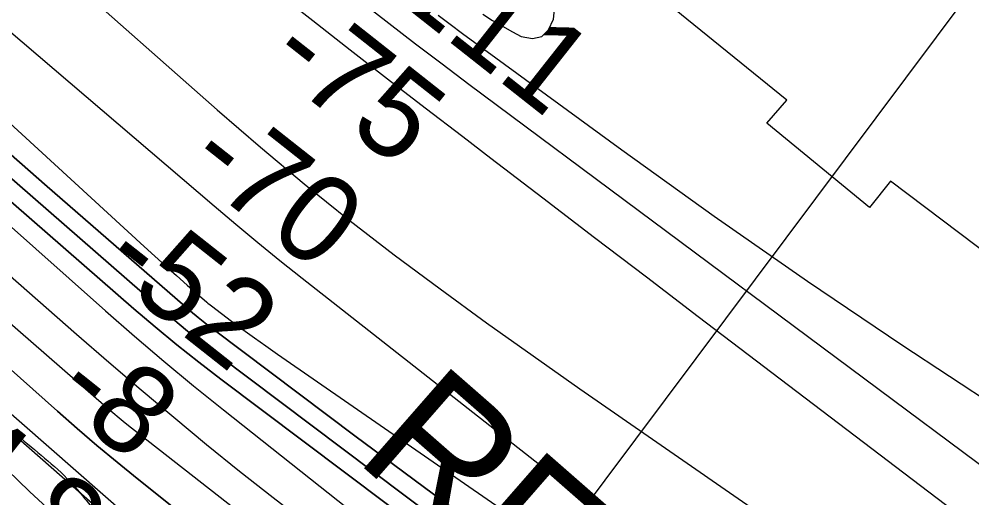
# Model space of a CAD drawing. Extents: x 3823584 to 3861785, y 301729 to 327625.
# Drawn here: x 3838296 to 3839018, y 323662 to 324025 of the extents above; entities that cross this region are included whole.
import ezdxf

# ---------------------------------------------------------------- set-up
doc = ezdxf.new("R2010")
doc.units = 0
for name, color, linetype in [('V-GRID-MAJR', 7, 'Continuous'), ('V-RIVR-EDGE', 7, 'Continuous'), ('V-RIVR-RANG', 7, 'Continuous'), ('V-RRAP-FSHR', 7, 'Continuous'), ('V-RRAP-RVMT', 7, 'Continuous'), ('V-RRAP-RVMT-IDEN', 7, 'Continuous'), ('V-SITE-VEGE', 7, 'Continuous'), ('V-TOPO-DPTH', 7, 'Continuous'), ('V-TOPO-MAJR', 7, 'Continuous'), ('V-TOPO-MINR', 7, 'Continuous'), ('V-TOPO-WATR', 7, 'Continuous')]:
    doc.layers.add(name, color=color, linetype=linetype)

msp = doc.modelspace()

# ---------------------------------------------------------------- linework, layer by layer
at = {"layer": 'V-GRID-MAJR'}
msp.add_spline([(3838444.89, 307319.34), (3838352.38, 313376.37), (3838259.82, 319436.47), (3838167.27, 325496.58), (3838167.22, 325499.66)], degree=3, dxfattribs=at)
at = {"layer": 'V-RIVR-EDGE'}
msp.add_spline([(3836304.38, 325474.18), (3836346.41, 325438.32), (3836389.41, 325406.07), (3836417.64, 325385.43), (3836442.67, 325366.73), (3836470.25, 325340.95), (3836497.82, 325313.88), (3836554.9, 325258.45), (3836598.51, 325215.91), (3836636.36, 325181.1), (3836681.26, 325139.85), (3836737.07, 325093.42), (3836790.94, 325041.22), (3836840.33, 324993.52), (3836889.07, 324947.12), (3836934.61, 324907.14), (3836980.81, 324871.03), (3837015.47, 324849.09), (3837040.49, 324829.1), (3837085.39, 324787.2), (3837143.76, 324734.34), (3837181.61, 324700.82), (3837223.29, 324659.57), (3837272.05, 324619.59), (3837314.38, 324579.63), (3837346.45, 324546.76), (3837364.4, 324527.43), (3837395.83, 324500.35), (3837442.02, 324462.31), (3837492.71, 324422.97), (3837554.31, 324372.67), (3837573.56, 324361.05), (3837583.2, 324359.1), (3837596.69, 324352.64), (3837621.08, 324337.79), (3837648.03, 324319.73), (3837677.54, 324292.01), (3837718.58, 324249.48), (3837753.85, 324214.68), (3837781.43, 324188.89), (3837800.05, 324179.85), (3837819.95, 324170.8), (3837850.72, 324134.08), (3837874.45, 324110.23), (3837909.07, 324073.5), (3837941.78, 324040.64), (3837989.87, 323991.66), (3838022.58, 323960.72), (3838034.12, 323947.83), (3838046.3, 323933.66), (3838066.83, 323916.25), (3838089.91, 323892.41), (3838140.59, 323849.21), (3838186.14, 323811.17), (3838215.65, 323785.38), (3838265.68, 323736.4), (3838297.1, 323707.39), (3838336.87, 323671.94), (3838359.95, 323645.52), (3838385.62, 323627.46), (3838404.24, 323615.84), (3838421.56, 323601.65), (3838441.44, 323582.32), (3838460.05, 323567.49), (3838468.4, 323563.61), (3838484.45, 323555.21), (3838548.59, 323496.55), (3838595.44, 323464.29), (3838649.98, 323422.37), (3838701.3, 323379.82), (3838749.43, 323345.62), (3838798.22, 323317.86), (3838856.62, 323274.64), (3838932.99, 323221.74), (3838989.47, 323184.31), (3839037.6, 323150.12), (3839068.42, 323134.62), (3839093.42, 323104.98), (3839110.73, 323086.94), (3839122.93, 323081.12), (3839143.46, 323065.64), (3839172.34, 323044.36), (3839190.96, 323032.74), (3839215.99, 323015.96), (3839242.32, 323006.26), (3839316.8, 322969.43), (3839341.84, 322955.87), (3839371.38, 322944.22), (3839391.29, 322935.81), (3839417.61, 322920.32), (3839461.26, 322894.5), (3839483.71, 322873.23), (3839520.3, 322851.28), (3839555.6, 322828.69), (3839599.9, 322806.72), (3839718.7, 322751.14), (3839768.14, 322726.59), (3839807.95, 322705.92), (3839836.85, 322696.21), (3839865.1, 322680.71), (3839887.57, 322667.8), (3839924.17, 322652.28), (3839969.76, 322630.31), (3840004.43, 322612.22), (3840037.82, 322597.35), (3840085.35, 322579.88), (3840108.46, 322565.68), (3840121.92, 322548.93), (3840123.18, 322539.92), (3840122.53, 322533.5), (3840118, 322521.29), (3840112.84, 322514.24), (3840095.47, 322509.14), (3840089.68, 322509.15), (3840085.17, 322504.66), (3840084.51, 322498.23), (3840085.78, 322491.8), (3840130.72, 322467.26), (3840169.89, 322448.52), (3840197.51, 322439.45), (3840209.08, 322437.5), (3840231.59, 322441.3), (3840246.39, 322448.98), (3840266.34, 322458.57), (3840273.43, 322466.27), (3840278.59, 322471.4), (3840288.9, 322480.37), (3840295.98, 322484.85), (3840301.77, 322484.84), (3840308.2, 322484.82), (3840320.4, 322479.01), (3840324.87, 322470), (3840326.78, 322461.63), (3840338.32, 322450.03), (3840344.74, 322444.88), (3840366.58, 322437.75), (3840385.84, 322428.06), (3840421.8, 322409.33), (3840466.1, 322385.43), (3840492.41, 322368.65), (3840506.53, 322357.04), (3840533.49, 322340.26), (3840559.18, 322331.2), (3840587.44, 322322.13), (3840611.85, 322311.78), (3840642.02, 322296.28), (3840678.62, 322276.26), (3840712.64, 322255.6), (3840733.18, 322242.05), (3840784.53, 322210.43), (3840835.89, 322183.3), (3840892.39, 322153.59), (3840923.85, 322139.37), (3840950.82, 322127.08), (3840989.33, 322099.99), (3841017.57, 322082.56), (3841061.24, 322062.52), (3841092.69, 322044.45), (3841151.1, 322005.09), (3841210.78, 321964.44), (3841240.29, 321939.29), (3841299.97, 321894.79), (3841335.89, 321862.55), (3841374.37, 321823.89), (3841411.57, 321789.72), (3841444.92, 321758.14), (3841469.94, 321736.22), (3841482.12, 321723.98), (3841496.22, 321704.66), (3841509.05, 321694.34), (3841523.18, 321687.23), (3841573.9, 321660.75), (3841623.97, 321631.69), (3841667.62, 321606.51), (3841696.52, 321593.59), (3841738.26, 321575.48), (3841787.07, 321556.72), (3841815.99, 321552.15), (3841851.33, 321544.99), (3841886.66, 321533.33), (3841930.32, 321511.36), (3841950.22, 321498.46), (3841977.18, 321482.96), (3841998.38, 321476.48), (3842052.99, 321463.49), (3842082.55, 321456.34), (3842109.52, 321444.7), (3842146.12, 321427.26), (3842196.2, 321402.06), (3842241.13, 321374.95), (3842288.63, 321345.26), (3842321.38, 321327.18), (3842366.94, 321295.56), (3842395.19, 321280.07), (3842429.22, 321264.55), (3842452.35, 321258.71), (3842470.97, 321249.66)], degree=3, dxfattribs=at)
at = {"layer": 'V-RIVR-RANG'}
msp.add_line((3838513.47, 323372.9), (3839031.51, 324065.62), dxfattribs=at)
at = {"layer": 'V-RRAP-FSHR'}
msp.add_lwpolyline([(3836295.02, 325470.8), (3836414.5, 325364.56), (3836758, 325057.8), (3837184.26, 324676.32), (3837417.66, 324483.21), (3837615.8, 324305.96), (3837777.41, 324176.43), (3837917.93, 324038.71), (3838584.55, 323453.18)], dxfattribs=at)
at = {"layer": 'V-RRAP-RVMT'}
for p, q in [((3838877.74, 323963.57), (3838787.12, 324036.91)), ((3838862.5, 323946.12), (3838877.74, 323963.57)), ((3838940.35, 323882.38), (3838862.5, 323946.12)), ((3838956.17, 323902.25), (3838940.35, 323882.38)), ((3839067.87, 323817.85), (3838956.17, 323902.25)), ((3838276.69, 323737.31), (3838377.61, 323648.95))]:
    msp.add_line(p, q, dxfattribs=at)
at = {"layer": 'V-SITE-VEGE'}
msp.add_lwpolyline([(3838244.56, 323724.06), (3838303.63, 323667), (3838353.84, 323620.5)], dxfattribs=at)
at = {"layer": 'V-TOPO-DPTH'}
for points in [[(3839047.78, 323301.81), (3838448.68, 323752.1), (3838431.86, 323765.04), (3838415.23, 323778.21), (3838398.88, 323791.75), (3838382.74, 323805.52), (3837860.93, 324260.56)], [(3839047.78, 323301.81), (3838448.68, 323752.1), (3838431.86, 323765.04), (3838415.23, 323778.21), (3838398.88, 323791.75), (3838382.74, 323805.52), (3837860.93, 324260.56)], [(3838153.68, 324022.86), (3838401.16, 323807.21), (3838412.21, 323797.79), (3838423.4, 323788.53), (3838434.78, 323779.51), (3838446.3, 323770.66), (3838752.96, 323540.12), (3838808.46, 323499.01), (3838864.34, 323458.43), (3838920.78, 323418.64), (3838977.6, 323379.38), (3839031.93, 323342.4)], [(3839031.93, 323342.4), (3838977.6, 323379.38), (3838920.78, 323418.64), (3838864.34, 323458.43), (3838808.46, 323499.01), (3838752.96, 323540.12), (3838446.3, 323770.66), (3838434.78, 323779.51), (3838423.4, 323788.53), (3838412.21, 323797.79), (3838401.16, 323807.21), (3838153.68, 324022.86)], [(3839103.1, 323135.17), (3839017.28, 323186.86), (3839013.04, 323189.49), (3839008.84, 323192.19), (3839004.71, 323194.99), (3839000.62, 323197.86), (3838924.64, 323252.69), (3838882.82, 323283.33), (3838841.31, 323314.37), (3838800.26, 323346.02), (3838759.52, 323378.07), (3838385.33, 323676.9), (3838369.99, 323689.35), (3838354.79, 323701.97), (3838339.79, 323714.83), (3838324.93, 323727.85), (3838008.71, 324009.46)], [(3838260.18, 323948.03), (3838317.14, 323898.11), (3838419.59, 323808.9), (3838425.54, 323803.83), (3838431.57, 323798.84), (3838437.7, 323793.98), (3838443.91, 323789.21), (3838550.19, 323709.3), (3838609.87, 323665.03), (3838669.92, 323621.28), (3838730.54, 323578.31), (3838791.52, 323535.86), (3839065.19, 323348)], [(3839065.19, 323348), (3838791.52, 323535.86), (3838730.54, 323578.31), (3838669.92, 323621.28), (3838609.87, 323665.03), (3838550.19, 323709.3), (3838443.91, 323789.21), (3838437.7, 323793.98), (3838431.57, 323798.84), (3838425.54, 323803.83), (3838419.59, 323808.9), (3838317.14, 323898.11), (3838260.18, 323948.03)], [(3838280.38, 323837.73), (3838339.24, 323786.21), (3838363.64, 323765.07), (3838388.18, 323744.08), (3838412.91, 323723.33), (3838437.79, 323702.74), (3838462.92, 323682.48), (3838488.28, 323662.5), (3838513.96, 323642.95), (3838539.86, 323623.68), (3839021.06, 323271.76)], [(3838280.38, 323837.73), (3838339.24, 323786.21), (3838363.64, 323765.07), (3838388.18, 323744.08), (3838412.91, 323723.33), (3838437.79, 323702.74), (3838462.92, 323682.48), (3838488.28, 323662.5), (3838513.96, 323642.95), (3838539.86, 323623.68), (3839021.06, 323271.76)]]:
    msp.add_lwpolyline(points, dxfattribs=at)
at = {"layer": 'V-TOPO-MAJR'}
for points in [[(3837784.65, 324408.95), (3838390.47, 323852.75), (3838398.58, 323845.37), (3838406.73, 323838.03), (3838414.93, 323830.75), (3838423.17, 323823.52), (3838438.02, 323810.6), (3838438.88, 323809.87), (3838440.63, 323808.46), (3838441.52, 323807.77), (3838456.82, 323796.26), (3838465.41, 323789.89), (3838474.05, 323783.58), (3838482.76, 323777.37), (3838491.53, 323771.23), (3839096.12, 323353.07)], [(3838613.26, 324028.04), (3838622.5, 324021.07), (3838631.81, 324014.19), (3838752.51, 323926.07), (3838822.64, 323875.8), (3838893.33, 323826.35), (3838964.85, 323778.12), (3839036.95, 323730.72), (3839242.36, 323598.18), (3839267.15, 323581.94), (3839291.81, 323565.49), (3839316.25, 323548.72), (3839340.54, 323531.74), (3839531.52, 323396.3), (3839611.58, 323339.84), (3839691.82, 323283.66), (3839772.35, 323227.88), (3839853.08, 323172.38), (3839964.66, 323096.08), (3839989.91, 323079.21), (3840015.39, 323062.71), (3840041.23, 323046.77), (3840067.29, 323031.19)]]:
    msp.add_lwpolyline(points, dxfattribs=at)
at = {"layer": 'V-TOPO-MINR'}
for points in [[(3837798.92, 324434.09), (3838443.61, 323883.46), (3838460.11, 323869.55), (3838476.71, 323855.77), (3838493.49, 323842.2), (3838510.38, 323828.77), (3838900.64, 323522.25), (3838938.31, 323493.12), (3838976.26, 323464.38), (3839014.63, 323436.21), (3839053.3, 323408.43)], [(3837715.94, 324378.16), (3838361.3, 323803.95), (3838383.25, 323784.75), (3838405.41, 323765.81), (3838427.9, 323747.25), (3838450.6, 323728.94), (3838603.2, 323608.01), (3838678.68, 323549.08), (3838754.72, 323490.9), (3838831.6, 323433.83), (3838909.05, 323377.5), (3839050.79, 323275.99)], [(3837860.93, 324260.56), (3838382.74, 323805.52), (3838398.88, 323791.75), (3838415.23, 323778.21), (3838431.86, 323765.04), (3838448.68, 323752.1), (3839047.78, 323301.81)], [(3838647.32, 324028.86), (3838654.59, 324024.06), (3838662.07, 324019.57), (3838669.68, 324015.3), (3838676.3, 324011.76), (3838684.87, 324010.45), (3838692.04, 324011.76), (3838697.12, 324016.99), (3838700.79, 324024.85), (3838708.81, 324105.54)], [(3838490.01, 324046.11), (3838518.26, 324023.89), (3838546.62, 324001.81), (3838575.02, 323979.79), (3838603.48, 323957.84), (3838631.98, 323935.95), (3838653.36, 323919.57), (3838692.61, 323889.56), (3838731.87, 323859.57), (3838771.17, 323829.62), (3838810.49, 323799.71), (3839191.78, 323509.93)], [(3838555.84, 324037.49), (3838575.92, 324021.87), (3838596.08, 324006.36), (3838616.36, 323991.01), (3838636.71, 323975.75), (3839193.51, 323561.52), (3839203.67, 323553.98), (3839213.84, 323546.45), (3839224.03, 323538.95), (3839234.22, 323531.46), (3839252.33, 323518.19), (3839254.64, 323516.51), (3839256.95, 323514.83), (3839270.42, 323505.09), (3839278.34, 323499.4), (3839286.27, 323493.75), (3839294.24, 323488.15), (3839302.24, 323482.58), (3839964.08, 323024.77), (3839972.37, 323019.14), (3839980.72, 323013.61), (3839989.17, 323008.24), (3839997.68, 323002.96), (3840082.33, 322951.49)], [(3838361.74, 324030.59), (3838411.39, 323986.61), (3838445.75, 323956.25), (3838478.6, 323927.91), (3838511.87, 323900.09), (3838545.78, 323873.04), (3838580.12, 323846.52), (3838614.92, 323820.6), (3838649.94, 323794.97), (3838685.26, 323769.77), (3838720.8, 323744.85), (3839168.79, 323434.74)], [(3838153.68, 324022.86), (3838401.16, 323807.21), (3838412.21, 323797.79), (3838423.4, 323788.53), (3838434.78, 323779.51), (3838446.3, 323770.66), (3838752.96, 323540.12), (3838808.46, 323499.01), (3838864.34, 323458.43), (3838920.78, 323418.64), (3838977.6, 323379.38), (3839031.93, 323342.4)], [(3838260.18, 323948.03), (3838317.14, 323898.11), (3838419.59, 323808.9), (3838425.54, 323803.83), (3838431.57, 323798.84), (3838437.7, 323793.98), (3838443.91, 323789.21), (3838550.19, 323709.3), (3838609.87, 323665.03), (3838669.92, 323621.28), (3838730.54, 323578.31), (3838791.52, 323535.86), (3839065.19, 323348)], [(3838280.38, 323837.73), (3838339.24, 323786.21), (3838363.64, 323765.07), (3838388.18, 323744.08), (3838412.91, 323723.33), (3838437.79, 323702.74), (3838462.92, 323682.48), (3838488.28, 323662.5), (3838513.96, 323642.95), (3838539.86, 323623.68), (3839021.06, 323271.76)], [(3838283, 323799.97), (3838362.09, 323730.98), (3838366.76, 323726.97), (3838371.47, 323723.02), (3838376.24, 323719.15), (3838381.05, 323715.32), (3838513.2, 323612.09), (3838584.47, 323557.15), (3838656.2, 323502.83), (3838728.61, 323449.42), (3838801.48, 323396.63), (3838984.4, 323265.88), (3839010.57, 323247.44), (3839036.89, 323229.24)]]:
    msp.add_lwpolyline(points, dxfattribs=at)
at = {"layer": 'V-TOPO-WATR'}
msp.add_lwpolyline([(3838008.71, 324009.46), (3838324.93, 323727.85), (3838339.79, 323714.83), (3838354.79, 323701.97), (3838369.99, 323689.35), (3838385.33, 323676.9), (3838759.52, 323378.07), (3838800.26, 323346.02), (3838841.31, 323314.37), (3838882.82, 323283.33), (3838924.64, 323252.69), (3839000.62, 323197.86), (3839004.71, 323194.99), (3839008.84, 323192.19), (3839013.04, 323189.49), (3839017.28, 323186.86), (3839103.1, 323135.17)], dxfattribs=at)

# ---------------------------------------------------------------- texts
at = {"layer": 'V-RIVR-RANG'}
for s, rotation, p in [('-111', 321.73497, (3838554.97, 324060.51)), ('-75', 321.73497, (3838481.45, 323991.14)), ('-70', 321.73497, (3838419.95, 323912.28)), ('-52', 321.73497, (3838355.14, 323836.05)), ('-8', 321.44833, (3838319.13, 323737.4)), ('4.8', 321.44833, (3838229.16, 323681.23))]:
    msp.add_text(s, height=67, rotation=rotation, dxfattribs=at).set_placement(p)
at = {"layer": 'V-RRAP-RVMT-IDEN'}
msp.add_text('REVET.', height=100, rotation=318.82628, dxfattribs=at).set_placement((3838548.98, 323691.93))

doc.saveas('drawing.dxf')
